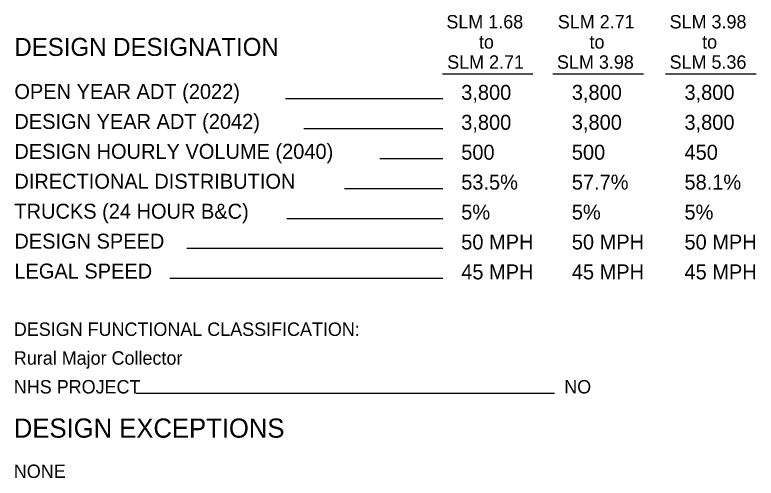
# Model space of a CAD drawing. Extents: x -59 to 82, y -3 to 49.
# Drawn here: x -54.99 to -47.26, y 34.09 to 38.92 of the extents above; entities that cross this region are included whole.
import ezdxf

# ---------------------------------------------------------------- set-up
doc = ezdxf.new("R2010")
doc.units = 0
doc.layers.add('SH_Data', color=7, linetype='Continuous')
doc.layers.add('SH_Text', color=7, linetype='Continuous')

msp = doc.modelspace()

# ---------------------------------------------------------------- linework, layer by layer
at = {"layer": 'SH_Data'}
for p, q in [((-50.5273, 38.0469), (-52.1678, 38.0469)), ((-50.5273, 37.7349), (-51.979, 37.7349)), ((-50.5273, 37.4229), (-51.1834, 37.4229)), ((-50.5273, 37.1109), (-51.5551, 37.1109)), ((-50.5273, 36.7989), (-52.1551, 36.7989)), ((-50.5273, 36.4869), (-53.1985, 36.4869)), ((-50.5273, 36.1749), (-53.3746, 36.1749)), ((-49.3612, 34.9766), (-53.7311, 34.9766))]:
    msp.add_line(p, q, dxfattribs=at)
at = {"layer": 'SH_Text'}
for p, q in [((-50.533, 38.3093), (-49.5878, 38.3093)), ((-49.3791, 38.3093), (-48.4339, 38.3093)), ((-48.2038, 38.3093), (-47.2586, 38.3093))]:
    msp.add_line(p, q, dxfattribs=at)

# ---------------------------------------------------------------- texts
at = {"layer": 'SH_Data'}
for s, height, p in [('DESIGN DESIGNATION', 0.1875, (-54.998, 38.496)), ('OPEN YEAR ADT (2022)', 0.156, (-54.998, 38.0469)), ('3,800', 0.15597, (-50.3359, 38.0378)), ('3,800', 0.15597, (-49.182, 38.0378)), ('3,800', 0.15597, (-48.0067, 38.0378)), ('DESIGN YEAR ADT (2042)', 0.156, (-54.998, 37.7349)), ('3,800', 0.15597, (-50.3359, 37.7258)), ('3,800', 0.15597, (-49.182, 37.7258)), ('3,800', 0.15597, (-48.0067, 37.7258)), ('DESIGN HOURLY VOLUME (2040)', 0.156, (-54.998, 37.4229)), ('500', 0.15597, (-50.3359, 37.4139)), ('500', 0.15597, (-49.182, 37.4139)), ('450', 0.15597, (-48.0067, 37.4139)), ('DIRECTIONAL DISTRIBUTION', 0.155966, (-54.998, 37.1109)), ('53.5%', 0.15597, (-50.3359, 37.102)), ('57.7%', 0.15597, (-49.182, 37.102)), ('58.1%', 0.15597, (-48.0067, 37.102)), ('TRUCKS (24 HOUR B&C)', 0.155966, (-54.998, 36.7989)), ('5%', 0.15597, (-50.3359, 36.79)), ('5%', 0.15597, (-49.182, 36.79)), ('5%', 0.15597, (-48.0067, 36.79)), ('DESIGN SPEED', 0.155966, (-54.998, 36.4868)), ('50 MPH', 0.15597, (-50.3359, 36.4781)), ('50 MPH', 0.15597, (-49.182, 36.4781)), ('50 MPH', 0.15597, (-48.0067, 36.4781)), ('LEGAL SPEED', 0.155966, (-54.998, 36.1748)), ('45 MPH', 0.15597, (-50.3359, 36.1662)), ('45 MPH', 0.15597, (-49.182, 36.1662)), ('45 MPH', 0.15597, (-48.0067, 36.1662))]:
    msp.add_text(s, height=height, dxfattribs=at).set_placement(p)
at = {"layer": 'SH_Text'}
for s, height, p in [('SLM 1.68', 0.14, (-50.4907, 38.7822)), ('SLM 2.71', 0.14, (-49.3285, 38.7822)), ('SLM 3.98', 0.14, (-48.1616, 38.7822)), ('to', 0.14, (-50.1513, 38.5722)), ('to', 0.14, (-48.9975, 38.5722)), ('to', 0.14, (-47.8222, 38.5722)), ('SLM 2.71', 0.14, (-50.4824, 38.3622)), ('SLM 3.98', 0.14, (-49.3368, 38.3622)), ('SLM 5.36', 0.14, (-48.1619, 38.3622)), ('DESIGN FUNCTIONAL CLASSIFICATION:', 0.14, (-55.0036, 35.5766)), ('Rural Major Collector', 0.14, (-55.0036, 35.2766)), ('NHS PROJECT', 0.14, (-55.0036, 34.9766)), ('NO', 0.14, (-49.2612, 34.9766)), ('DESIGN EXCEPTIONS', 0.2, (-55.0036, 34.5156)), ('NONE', 0.14, (-55.0036, 34.0956))]:
    msp.add_text(s, height=height, dxfattribs=at).set_placement(p)

doc.saveas('drawing.dxf')
